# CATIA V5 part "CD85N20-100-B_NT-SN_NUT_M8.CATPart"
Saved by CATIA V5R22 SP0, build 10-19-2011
Part number: CD85N20-100-B_NT-SN_NUT_M8
Revision: ANY
Definition: UNKNOWN
Nomenclature: CD85N20-100-B_NT-SN_NUT_M8
Source: Unknown
Bounding box of the stored display mesh (mm): x -6.5 to 6.5, y -7.506 to 7.506, z -2.5 to 2.5
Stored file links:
  U:\S9A\PER\CAO\Assemblage\Reservoir_Flacon\Verin\Poussoir_2\CD85N20-100-B_NT-SN_NUT_M8.CATPart
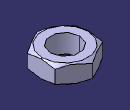
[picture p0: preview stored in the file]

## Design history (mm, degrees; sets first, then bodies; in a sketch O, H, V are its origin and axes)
Body1 "REVOLVE" (main body)
  Solid1: solid without history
